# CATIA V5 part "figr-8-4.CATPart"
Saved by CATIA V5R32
Part number: Part1
Bounding box of the stored display mesh (mm): x 4.549 to 89.781, y -52.238 to 26.36, z 54 to 147.773
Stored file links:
  D:\PROJECTS\Project 2022\CATIA V5 6R 2022\Resources\Part Files\c08_catia_v5_6r2022_prt\figr-8-4.CATPart
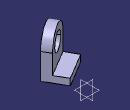
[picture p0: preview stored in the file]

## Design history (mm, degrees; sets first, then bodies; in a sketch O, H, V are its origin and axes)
Body1 (main body)
  Sketch1 on yz-plane, origin (0, 0, 0), H (0, 1, 0), V (0, 0, 1)
    point P1 (-104.4861, 0)
    line L1 (-104.4861, 0) -> (-104.4861, 44.267)
    arc A1 centre (-69.7903, 44.267) radius 34.6958 from (-104.4861, 44.267) to (-35.0946, 44.267) cw
    line L2 (-35.0946, 44.267) -> (-35.0946, 0)
    point P5 (-35.0946, 0)
    line L3 (-35.0946, 0) -> (-104.4861, 0)
    circle A2 centre (-69.7903, 44.267) radius 19.5413
    coincidence: P1 H, P5 H
    vertical: L1 V
    tangency: A1 L1, L2 A1
    horizontal: L3 H
  Pad1: profile Sketch1, direction (1, 0, 0), length 20
  Sketch2 on face of Pad1, origin (0, 0, 0), H (0, -1, 0), V (0, 0, 1)
    point P1 (35.0946, 0)
    line L1 (35.0946, 0) -> (104.4861, 0)
    line L2 (104.4861, 0) -> (104.4861, -15)
    line L3 (104.4861, -15) -> (35.0946, -15)
    line L4 (35.0946, -15) -> (35.0946, 0)
    reference projected line E1 (35.0946, 0) -> (35.0946, 44.267) from edge [face of Pad1 | face of Pad1]
    reference projected line E2 (104.4861, 44.267) -> (104.4861, 0) from edge [face of Pad1 | face of Pad1]
    distance L3 L1 = 15
    coincidence: P1 H, L4 E1, L2 E2
    horizontal: L1 H, L3 H
    vertical: L2 V, L4 V
  Pad2: profile Sketch2, direction (1, 0, 0), length 50
  Translate1: Direction xy-plane, ToTransfor Pad2, Length 69
  Rotate1: Axis edge, ToTransfor Translate1, Angle 121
